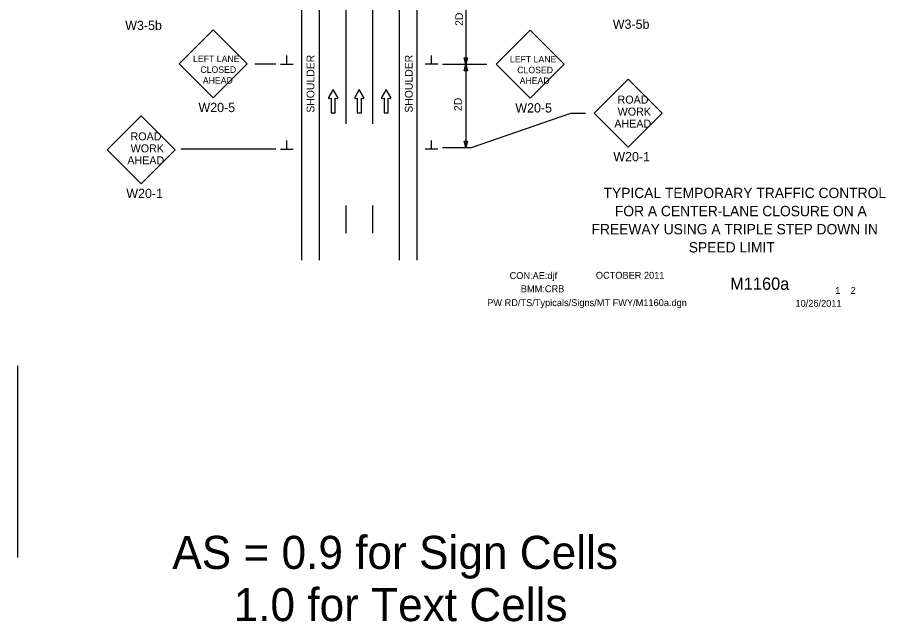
# Model space of a CAD drawing. Extents: x 16648 to 18482, y 5650 to 7013.
# Drawn here: x 16648 to 17429, y 5650 to 6193 of the extents above; entities that cross this region are included whole.
import ezdxf

# ---------------------------------------------------------------- set-up
doc = ezdxf.new("R2010")
doc.units = 0
for name, color, linetype in [('ALI_LEGAL_EX', 7, 'Continuous'), ('BORDER', 7, 'Continuous'), ('BORDER_SIGNAL_WO', 7, 'Continuous'), ('MT_SCRATCH_LEVEL_E', 7, 'Continuous'), ('PAVT_EDGE_EX', 7, 'Continuous'), ('TRAFFIC_SIGNS_PR', 7, 'Continuous'), ('TYPICAL_TEXT_DIMEN_PR', 7, 'Continuous')]:
    doc.layers.add(name, color=color, linetype=linetype)

msp = doc.modelspace()

# ---------------------------------------------------------------- linework, layer by layer
at = {"layer": 'ALI_LEGAL_EX'}
for p, q in [((16943.36, 6961.56), (16943.36, 6097.65)), ((16967.36, 6961.56), (16967.36, 6097.65))]:
    msp.add_line(p, q, dxfattribs=at)
for points in [[(16943.36, 6124.34), (16943.36, 6105.42)], [(16943.36, 6124.34), (16943.36, 6099.34)], [(16967.36, 6124.34), (16967.36, 6105.42)], [(16967.36, 6124.34), (16967.36, 6099.34)], [(16943.36, 6024.34), (16943.36, 5999.34)], [(16967.36, 6024.34), (16967.36, 5999.34)]]:
    msp.add_lwpolyline(points, dxfattribs=at)
at = {"layer": 'MT_SCRATCH_LEVEL_E'}
for p, q in [((16931.92, 6128.45), (16927.81, 6121.22)), ((16936.06, 6121.22), (16931.92, 6128.45)), ((16955.46, 6128.45), (16951.35, 6121.22)), ((16959.61, 6121.22), (16955.46, 6128.45)), ((16979.53, 6128.45), (16975.42, 6121.22)), ((16983.68, 6121.22), (16979.53, 6128.45)), ((16928.29, 6120.53), (16930.06, 6120.85)), ((16930.06, 6120.85), (16930.06, 6107.59)), ((16933.81, 6107.59), (16933.81, 6120.85)), ((16933.81, 6120.85), (16935.58, 6120.53)), ((16951.83, 6120.53), (16953.61, 6120.85)), ((16953.61, 6120.85), (16953.61, 6107.59)), ((16957.35, 6107.59), (16957.35, 6120.85)), ((16957.35, 6120.85), (16959.13, 6120.53)), ((16975.91, 6120.53), (16977.68, 6120.85)), ((16977.68, 6120.85), (16977.68, 6107.59)), ((16981.42, 6107.59), (16981.42, 6120.85)), ((16981.42, 6120.85), (16983.2, 6120.53)), ((16930.06, 6107.59), (16933.81, 6107.59)), ((16953.61, 6107.59), (16957.35, 6107.59)), ((16977.68, 6107.59), (16981.42, 6107.59))]:
    msp.add_line(p, q, dxfattribs=at)
for centre, start, end in [((16928.21, 6120.99), 150.42484, 279.96381), ((16935.65, 6120.99), 260.03619, 29.77312), ((16951.76, 6120.99), 150.42484, 279.96381), ((16959.2, 6120.99), 260.03619, 29.77312), ((16975.83, 6120.99), 150.42484, 279.96381), ((16983.27, 6120.99), 260.03619, 29.77312)]:
    msp.add_arc(centre, 0.463, start, end, dxfattribs=at)
at = {"layer": 'PAVT_EDGE_EX'}
for p, q in [((16903.36, 6926.44), (16903.36, 5975.16)), ((16919.36, 6926.44), (16919.36, 5975.16)), ((16991.36, 6926.44), (16991.36, 5975.16)), ((17007.36, 6926.44), (17007.36, 5975.16))]:
    msp.add_line(p, q, dxfattribs=at)
at = {"layer": 'TRAFFIC_SIGNS_PR'}
for p, q in [((16824.03, 6182.15), (16793.48, 6151.61)), ((16854.58, 6151.61), (16824.03, 6182.15)), ((17109.15, 6181.81), (17078.61, 6151.26)), ((17139.7, 6151.26), (17109.15, 6181.81)), ((16793.48, 6151.61), (16824.03, 6121.06)), ((16824.03, 6121.06), (16854.58, 6151.61)), ((17078.61, 6151.26), (17109.15, 6120.72)), ((17109.15, 6120.72), (17139.7, 6151.26)), ((17197.35, 6137.91), (17166.81, 6107.36)), ((17227.9, 6107.36), (17197.35, 6137.91)), ((16759.11, 6104.86), (16728.56, 6074.31)), ((16789.65, 6074.31), (16759.11, 6104.86)), ((17166.81, 6107.36), (17197.35, 6076.81)), ((17197.35, 6076.81), (17227.9, 6107.36)), ((16728.56, 6074.31), (16759.11, 6043.77)), ((16759.11, 6043.77), (16789.65, 6074.31)), ((16647.75, 5880), (16647.75, 5707.72))]:
    msp.add_line(p, q, dxfattribs=at)
at = {"layer": 'TYPICAL_TEXT_DIMEN_PR'}
for p, q in [((17051.36, 6226.26), (17051.36, 6151.26)), ((16890.23, 6151.41), (16890.23, 6159.2)), ((17020.48, 6151.41), (17020.48, 6159.2)), ((17051.36, 6151.26), (17049.79, 6157.12)), ((17049.79, 6157.12), (17051.36, 6157.12)), ((17051.36, 6157.12), (17052.93, 6157.12)), ((17052.93, 6157.12), (17051.36, 6151.26)), ((16880.36, 6151.41), (16861.36, 6151.41)), ((16884.61, 6151.41), (16895.86, 6151.41)), ((17026.11, 6151.41), (17014.86, 6151.41)), ((17030.36, 6151.26), (17070.28, 6151.26)), ((17049.79, 6145.4), (17051.36, 6151.26)), ((17051.36, 6151.26), (17051.36, 6076.26)), ((17051.36, 6151.26), (17052.93, 6145.4)), ((17051.36, 6145.4), (17049.79, 6145.4)), ((17052.93, 6145.4), (17051.36, 6145.4)), ((17056.36, 6076.26), (17145.67, 6107.39)), ((17145.67, 6107.39), (17158.88, 6107.39)), ((16890.23, 6074.77), (16890.23, 6082.55)), ((17020.48, 6074.77), (17020.48, 6082.55)), ((17051.36, 6076.26), (17049.79, 6082.12)), ((17049.79, 6082.12), (17051.36, 6082.12)), ((17051.36, 6082.12), (17052.93, 6082.12)), ((17052.93, 6082.12), (17051.36, 6076.26)), ((16880.36, 6074.77), (16794.73, 6074.77)), ((16884.61, 6074.77), (16895.86, 6074.77)), ((17026.11, 6074.77), (17014.86, 6074.77)), ((17030.36, 6076.26), (17056.36, 6076.26))]:
    msp.add_line(p, q, dxfattribs=at)

# ---------------------------------------------------------------- texts
at = {"layer": 'BORDER'}
for s, p in [('TYPICAL TEMPORARY TRAFFIC CONTROL', (17175.21, 6030.86)), ('FOR A CENTER-LANE CLOSURE ON A', (17185.42, 6014.56)), ('FREEWAY USING A TRIPLE STEP DOWN IN ', (17164.42, 5998.26)), ('SPEED LIMIT', (17251.92, 5981.96))]:
    msp.add_text(s, height=9.3, dxfattribs=at).set_placement(p)
at = {"layer": 'BORDER_SIGNAL_WO'}
for s, height, p in [('CON:AE:djf  ', 6.2, (17090.69, 5958.06)), ('    OCTOBER 2011    ', 6.2, (17159.08, 5958.34)), ('    M1160a   ', 11, (17272.86, 5948.38)), ('BMM:CRB   ', 6.2, (17100.81, 5946.17)), (' 1    2 ', 6.2, (17381.45, 5944.7)), ('PW RD/TS/Typicals/Signs/MT FWY/M1160a.dgn      ', 6.2, (17070.55, 5933.71)), ('10/26/2011    ', 6.2, (17347.93, 5933.13)), ('AS = 0.9 for Sign Cells', 29.7271, (16787.14, 5697.35)), ('     1.0 for Text Cells', 29.7271, (16787.14, 5650.34))]:
    msp.add_text(s, height=height, dxfattribs=at).set_placement(p)
at = {"layer": 'TRAFFIC_SIGNS_PR'}
for s, height, p in [('W3-5b', 8.37, (16744.82, 6182.04)), ('W3-5b', 8.37, (17183.56, 6183.1)), ('LEFT LANE', 5.85, (16805.9, 6153.18)), ('LEFT LANE', 5.85, (17091.02, 6152.84)), ('CLOSED', 5.85, (16812.46, 6143.51)), ('CLOSED', 5.85, (17097.58, 6143.16)), ('AHEAD', 5.85, (16814.65, 6133.83)), ('AHEAD', 5.85, (17099.77, 6133.49)), ('ROAD', 7.2, (17187.84, 6115.84)), ('W20-5', 8.37, (16810.73, 6108.19)), ('W20-5', 8.37, (17095.85, 6107.85)), ('WORK', 7.2, (17187.96, 6105.04)), ('AHEAD', 7.2, (17184.94, 6094.24)), ('ROAD', 7.2, (16749.59, 6082.79)), ('WORK', 7.2, (16749.71, 6071.99)), ('W20-1', 8.37, (17184.05, 6063.94)), ('AHEAD', 7.2, (16746.69, 6061.19)), ('W20-1', 8.37, (16745.8, 6030.9))]:
    msp.add_text(s, height=height, dxfattribs=at).set_placement(p)
at = {"layer": 'TYPICAL_TEXT_DIMEN_PR'}
for s, p in [('2D', (17048.8, 6185.73)), ('SHOULDER', (16915.04, 6107.71)), ('SHOULDER', (17003.47, 6107.71)), ('2D', (17047.68, 6109.16))]:
    msp.add_text(s, height=7, rotation=90, dxfattribs=at).set_placement(p)

doc.saveas('drawing.dxf')
